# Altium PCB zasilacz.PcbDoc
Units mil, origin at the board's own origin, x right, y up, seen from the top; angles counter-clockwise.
Board outline 8820.03 x 6925.02 mil, 2 copper layers (Top Layer, Bottom Layer); 56 components, 28 nets, 174 pads, 4 vias.
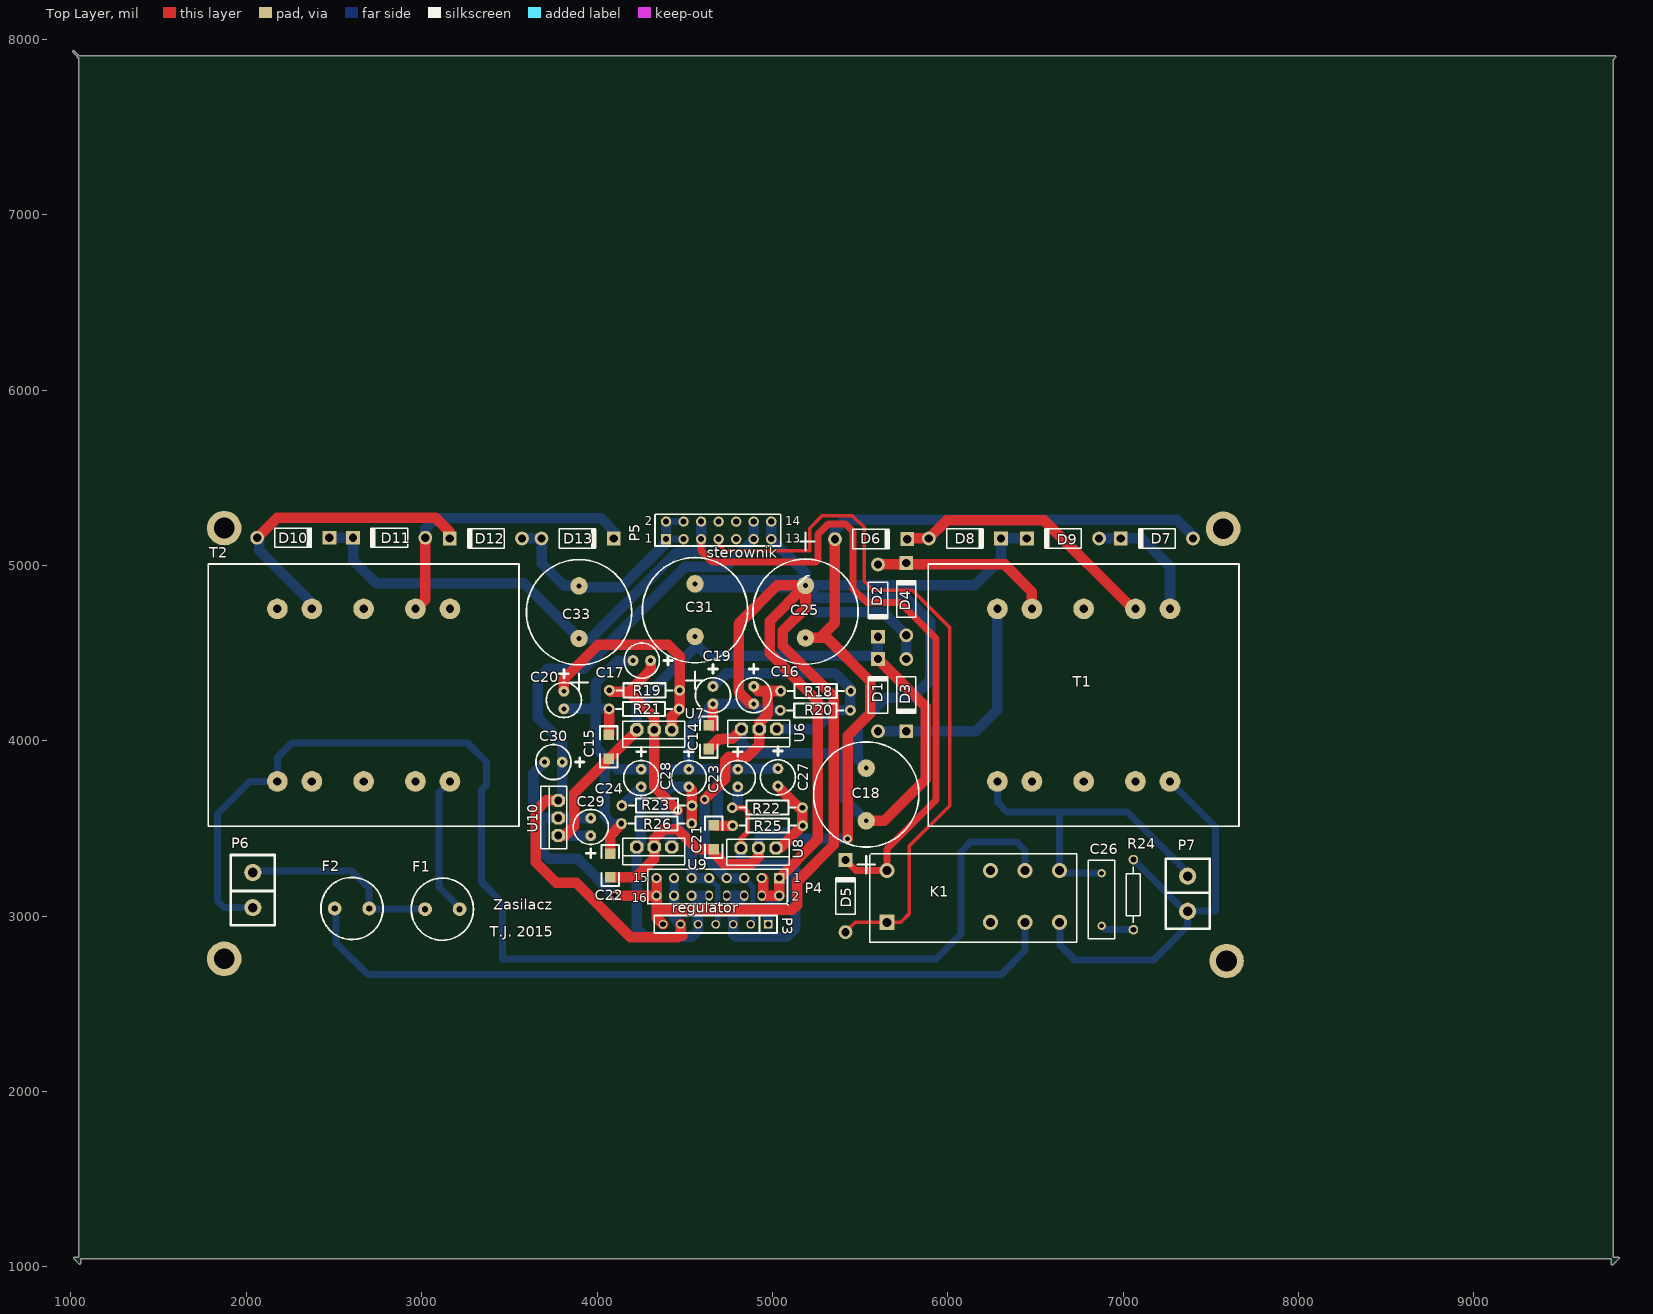
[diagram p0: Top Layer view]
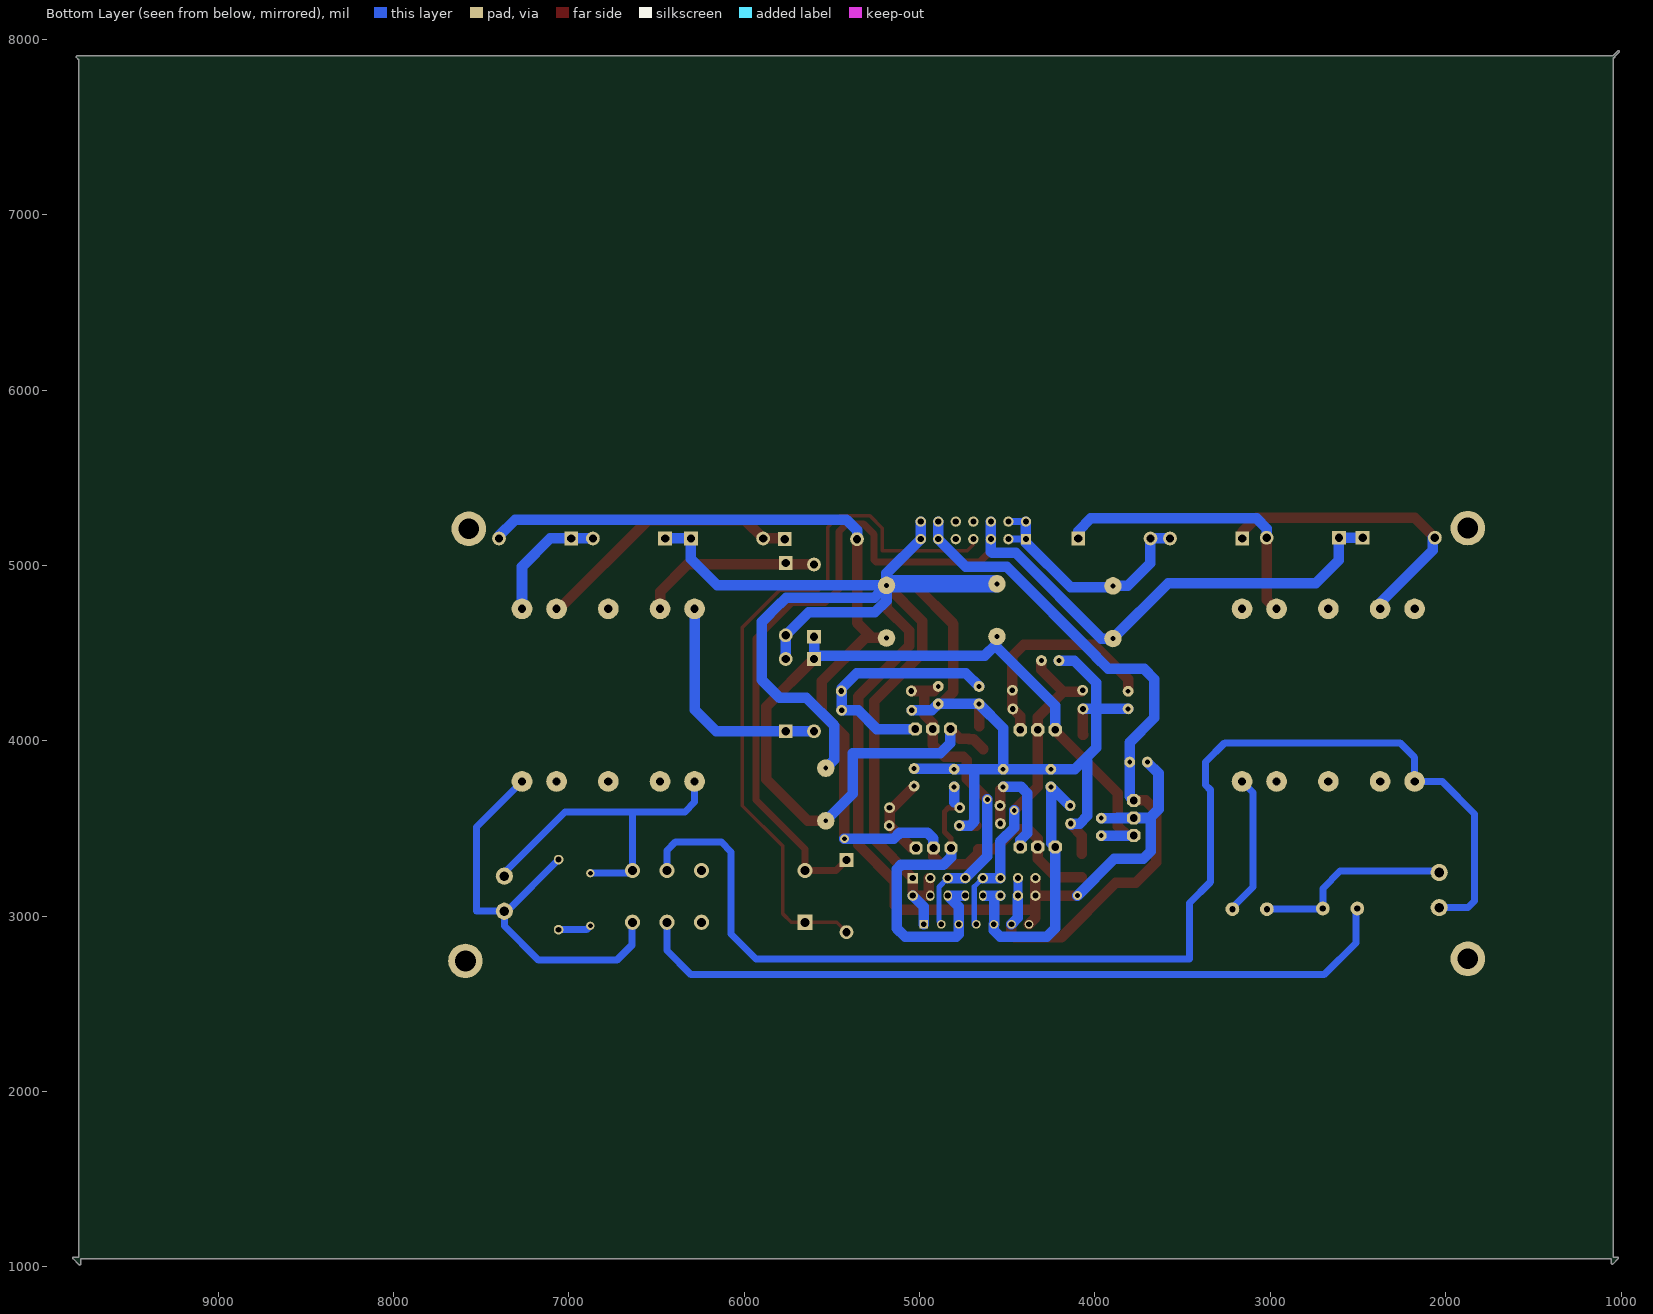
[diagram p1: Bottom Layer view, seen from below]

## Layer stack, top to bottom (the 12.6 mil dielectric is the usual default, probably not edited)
Top Solder: solder mask 0.4, Solder Resist, Dk 3.5
Top Layer: signal copper 1.4
Dielectric 1: dielectric 12.6, FR-4, Dk 4.8
Bottom Layer: signal copper 1.4
Bottom Solder: solder mask 0.4, Solder Resist, Dk 3.5

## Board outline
1016.47,1046.44 cw(c1020,1050) 1020,1055.02 1044.98,1055.02 1044.98,7892.92 1042.92,7894.98 1040,7894.98 cw(c1040,7900) 1035.57,7902.34 1011.45,7926.45 cw(c1015,7930) 1018.55,7933.55 1047.08,7905.02 9805,7905.02 cw(c9805,7900) 9810.01,7900 cw(c9805,7900) 9808.53,7896.44 9808.55,7896.45 9795.01,7882.92 9795.01,1055.02 9825,1055.02 cw(c9825,1050) 9830.01,1050 cw(c9825,1050) 9828.53,1046.44 9828.55,1046.45 9793.55,1011.45 9793.56,1011.47 cw(c9790,1015) 9784.99,1015 9784.99,1044.98 1055.02,1044.98 1055.02,1020 cw(c1050,1020) 1046.44,1016.47 1046.45,1016.45

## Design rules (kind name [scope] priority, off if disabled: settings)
Clearance [All] p1: gap=10
PolygonConnect [All] p1: connectstyle=Relief reliefconductorwidth=10 reliefentries=4 polygonreliefangle="90 Angle" airgapwidth=10
RoomDefinition zasilacz [InComponentClass('zasilacz')] p1: confinementstyle=ConfineIn formatcopy=TRUE lockcomponents=FALSE outline 9875,1660 28675,1660 28675,4910 9875,4910
RoutingVias [All] p1: holewidth=28 width=50 viastyle="Through Hole" minholewidth=28 minwidth=50 maxholewidth=28 maxwidth=50
SolderMaskExpansion [All] p1: expansion=4
Width [All] p1: maxlimit=40 minlimit=40 preferedwidth=40
30 further rules are at their usual default settings.

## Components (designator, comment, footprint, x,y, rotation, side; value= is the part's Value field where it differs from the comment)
C14 "Cap" 1206 4637.8,3952.76 r90 top
C15 "Cap" 1206 4066.93,3897.64 r90 top
C16 "ELECTRO2" RB.1/.2 4893.7,4409.45 r90 top
C17 "ELECTRO2" RB.1/.2 4405.51,4456.69 r0 top
C18 "ELECTRO2" RB.3/.6 5535.43,3543.31 r270 top
C19 "ELECTRO2" RB.1/.2 4661.42,4409.45 r90 top
C20 "ELECTRO2" RB.1/.2 3811.02,4381.89 r90 top
C21 "Cap" 1206 4665.35,3381.89 r90 top
C22 "Cap" 1206 4074.8,3220.47 r90 top
C23 "ELECTRO2" RB.1/.2 4803.15,3937.01 r90 top
C24 "ELECTRO2" RB.1/.2 4251.97,3937.01 r90 top
C25 "ELECTRO2" RB.3/.6 5188.98,4885.83 r90 top
C26 "Cap" RAD-0.3 6877.95,3094.49 r90 top
C27 "ELECTRO2" RB.1/.2 5031.5,3940.94 r90 top
C28 "ELECTRO2" RB.1/.2 4523.62,3937.01 r90 top
C29 "ELECTRO2" RB.1/.2 3964.57,3358.27 r270 top
C30 "ELECTRO2" RB.1/.2 3901.57,3877.95 r0 top
C31 "ELECTRO2" RB.3/.6 4559.06,4594.49 r270 top
C33 "ELECTRO2" RB.3/.6 3897.64,4582.68 r270 top
D1 "Diode 1N4001" DO-41 5602.36,4259.84 r90 top
D2 "Diode 1N4001" DO-41 5602.36,4799.21 r270 top
D3 "Diode 1N4001" DO-41 5763.78,4259.84 r270 top
D4 "Diode 1N4001" DO-41 5763.78,4807.09 r90 top
D5 "Diode 1N4007" DO-41 5417.32,3114.17 r90 top
D6 "Diode 1N4001" DO-41 5562.99,5149.61 r0 top
D7 "Diode 1N4001" DO-41 7192.91,5153.54 r180 top
D8 "Diode 1N4001" DO-41 6098.43,5153.54 r0 top
D9 "Diode 1N4001" DO-41 6657.48,5153.54 r180 top
D10 "Diode 1N4001" DO-41 2267.72,5157.48 r0 top
D11 "Diode 1N4001" DO-41 2814.96,5157.48 r180 top
D12 "Diode 1N4001" DO-41 3366.14,5153.54 r180 top
D13 "Diode 1N4001" DO-41 3889.76,5153.54 r0 top
F1 "Fuse 1" BEZP_OKR 3118.11,3039.37 r0 top
F2 "Fuse 1" BEZP_OKR 2602.36,3043.31 r180 top
K1 "Relay-DPDT" Prz_big 5653.54,2964.57 r90 top
P3 "regulator" SIP7 4976.38,2952.76 r180 top
P4 "regulator" HDR2X8 5039.37,3216.54 r180 top
P5 "sterownik" HDR2X7 4393.7,5149.61 r0 top
P6 "230VAC" ZLSRUB2-1 2066.93,3118.11 r90 top
P7 "230VAC_OUT" ZLSRUB2-1 7338.58,3157.48 r270 top
R18 "RES2" AXIAL0.4 5047.24,4283.46 r0 top
R19 "RES2" AXIAL0.4 4070.87,4287.4 r0 top
R20 "RES2" AXIAL0.4 5444.88,4173.23 r180 top
R21 "RES2" AXIAL0.4 4468.5,4181.1 r180 top
R22 "RES2" AXIAL0.4 4771.65,3618.11 r0 top
R23 "RES2" AXIAL0.4 4141.73,3629.92 r0 top
R24 "Res2" AXIAL-0.4 7059.06,3122.05 r270 top
R25 "RES2" AXIAL0.4 5173.23,3515.75 r180 top
R26 "RES2" AXIAL0.4 4539.37,3527.56 r180 top
T1 "trafo ZZ2" "TRAFO ZZ7" 6775.59,4259.84 r180 top
T2 "trafo ZZ1" "TRAFO ZZ7" 2669.29,4259.84 r180 top
U6 "LM317" 78XXST 5000,4051.18 r180 top
U7 "LM317" 78XXST 4401.57,4047.24 r180 top
U8 "LM337" 78XXST 4996.06,3374.02 r180 top
U9 "LM337" 78XXST 4401.57,3377.95 r180 top
U10 "7805" 78XXST 3763.78,3484.25 r90 top

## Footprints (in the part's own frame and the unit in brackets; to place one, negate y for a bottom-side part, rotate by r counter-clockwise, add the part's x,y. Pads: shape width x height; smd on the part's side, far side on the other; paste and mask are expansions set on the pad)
78XXST [mil]
  oct 75x75 hole 45: 1(-25,-15) 2(75,-15) 3(175,-15)
  silkscreen extent -100,-65 255,85
1206 [mil]
  rect 60x60 smd: 1(0,0) 2(135,0)
  silkscreen extent -50,-50 185,50
AXIAL0.4 [mil]
  round 62 hole 32: 1(0,0) 2(400,0)
  silkscreen extent 40,-40 360,40
AXIAL-0.4 [mm] "Axial Device, Thru-Hole; 2 Leads; 0.4 in Pin Spacing"
  round 1.4 hole 0.85: 1(-5.08,0) 2(5.08,0)
  silkscreen extent -4.06,-1.02 4.06,1.02
BEZP_OKR [mm]
  round 2 hole 0.9: 1(-2.5,0) 2(2.5,0)
  silkscreen extent -4.5,-4.5 4.5,4.5
DO-41 [mm] "Diode, Axial; Body 5.2 x 2.7 mm (LxDia. max), Lead Dia. 0.86 mm (max)"
  round 2 hole 1.2: 1(-5.23,0)
  rect 2x2 hole 1.2: 2(5.23,0)
  silkscreen extent -2.65,-1.4 2.75,1.4
HDR2X7 [mm] "Connector; Header; 7x2 Position"
  rect 1.5x1.5 hole 0.9: 1(0,0)
  round 1.5 hole 0.9: 2(0,2.54) 3(2.54,0) 4(2.54,2.54) 5(5.08,0) 6(5.08,2.54) 7(7.62,0) 8(7.62,2.54) 9(10.16,0) 10(10.16,2.54) 11(12.7,0) 12(12.7,2.54) 13(15.24,0) 14(15.24,2.54)
HDR2X8 [mm] "Connector; Header; 8x2 Position"
  rect 1.5x1.5 hole 0.9: 1(0,0)
  round 1.5 hole 0.9: 2(0,2.54) 3(2.54,0) 5(5.08,0) 7(7.62,0) 9(10.16,0) 11(12.7,0) 12(12.7,2.54) 13(15.24,0) 14(15.24,2.54) 15(17.78,0) 16(17.78,2.54)
  oval 1.2x1.5 hole 0.9: 4(2.54,2.54) 6(5.08,2.54)
  oval 1.1x1.5 hole 0.9: 8(7.62,2.54) 10(10.16,2.54)
  silkscreen extent 19.05,-1.27 19.05,3.81
Prz_big [mm]
  round 2.2 hole 1.3: 1(0,-20) 2(0,-15) 3(0,-25) 4(7.5,-20) 5(7.5,-15) 6(7.5,-25) 8(7.5,0)
  rect 2.2x2.2 hole 1.3: 7(0,0)
  silkscreen extent -2.92,-27.5 9.91,2.5
RAD-0.3 [mm] "Radial Cap, Thru-Hole; 2 Leads; 0.3 in Pin Spacing"
  round 1.2 hole 0.7: 1(-3.81,0) 2(3.81,0)
  silkscreen extent -5.71,-1.91 5.71,1.91
RB.1/.2 [mil]
  round 62 hole 28: 1(-100,0) 2(-200,0)
  silkscreen extent -250,-100 25,100
RB.3/.6 [mil]
  round 100 hole 28: 1(0,0) 2(-300,0)
  silkscreen extent -450,-300 300,300
SIP7 [mil]
  rect 50x50 hole 32: 1(0,0)
  round 50 hole 32: 2(100,0) 3(200,0) 4(300,0) 5(400,0) 6(500,0) 7(600,0)
  silkscreen extent -50,-50 650,50
"TRAFO ZZ7" [mm]
  round 3 hole 1.2: 1(-12.5,12.5) 2(-7.5,12.5) 3(0,12.5) 4(7.5,12.5) 5(12.5,12.5) 6(12.5,-12.5) 7(7.5,-12.5) 8(0,-12.5) 9(-7.5,-12.5) 10(-12.5,-12.5)
  silkscreen extent -22.5,-19 22.5,19
ZLSRUB2-1 [mil]
  round 98 hole 55: 1(-70,30) 2(130,30)
  silkscreen extent -170,-95 230,155

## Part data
C14 C15 C21 C22 C26: "Capacitor"
C16 C17 C18 C19 C20 C23 C24 C25 C27 C28 C29 C30 C31 C33: "Electrolytic Capacitor"
D1 D2 D3 D4 D5 D6 D7 D8 D9 D10 D11 D12 D13: "1 Amp General Purpose Rectifier"
F1 F2: "Fuse"
K1: "Dual-Pole Dual-Throw Relay"
P3: library part MHDR1X7, "Header, 7-Pin"
P4: library part "Header 8X2", "Header, 8-Pin, Dual row"
P5: library part "Header 7X2", "Header, 7-Pin, Dual row"
P6 P7: library part "Header 2", "Header, 2-Pin"
R24: "Resistor"
U10: library part 78XX

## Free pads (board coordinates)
  round 196.85 hole 118.11: 0(1874.02,2755.91) 0(1874.02,5212.6) 0(7570.87,5208.66) 0(7590.55,2744.09)

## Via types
v1: diameter 50, hole 28, Top Layer to Bottom Layer, 4 vias

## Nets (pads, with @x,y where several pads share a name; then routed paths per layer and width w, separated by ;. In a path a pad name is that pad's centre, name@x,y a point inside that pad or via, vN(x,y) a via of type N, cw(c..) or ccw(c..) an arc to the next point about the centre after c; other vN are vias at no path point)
230VAC1: K1.3 P7.2 R24.1 T1.1 | length 2498.3
  Bottom Layer w40: K1.3 6641.73,2960.63 6641.73,2833.54 6727.24,2748.03 7173.23,2748.03 7368.58,2943.39 P7.2 ; R24.1 7353.62,3027.48 P7.2 ; T1.1 7527.56,3507.87 7527.56,3027.56 7527.48,3027.48 P7.2
230VAC2: C26.2 K1.6 P7.1 T1.5 | length 1973.8
  Bottom Layer w40: T1.5 6283.46,3649.61 6338.58,3594.49 6641.73,3594.49 ; C26.2 6653.15,3244.49 K1.6 6637.8,3590.55 6641.73,3594.49 ; P7.1 7368.58,3249.53 7023.62,3594.49 6641.73,3594.49
230VAC3: F1.2 T2.1 | length 801.1
  Bottom Layer w40: T2.1 3098.43,3704.72 3098.43,3165.35 F1.2@3220.47,3043.31
230VAC4: F2.2 K1.1 | length 4431.3
  Bottom Layer w40: F2.2@2511.81,3055.12 2511.81,2846.46 2692.91,2665.35 6303.15,2665.35 6440.94,2803.15 K1.1
230VAC5: K1.4 P6.1 T2.5 | length 7390.6
  Bottom Layer w40: P6.1 1873.15,3048.11 1834.65,3086.61 1834.65,3582.68 2019.68,3767.72 T2.5 2177.17,3905.51 2259.84,3988.19 3259.84,3988.19 3370.08,3877.95 3370.08,3748.03 3342.52,3720.47 3342.52,3192.91 3460.63,3074.8 3460.63,2755.91 5933.07,2755.91 6074.8,2897.64 6074.8,3366.14 6129.92,3421.26 6393.7,3421.26 6440.94,3374.02 K1.4
+5VA: C17.1 P3.4 P4.9 P4.11 R19.1 U7.2 | length 1941.9
  Top Layer w60: R19.1 4078.74,4279.53 4181.1,4279.53 ; C17.1 4305.51,4403.94 4181.1,4279.53 ; v1(4460.63,3602.36) 4326.57,3736.42 U7.2 4326.57,4134.06 4181.1,4279.53
  Bottom Layer w30: P4.9 4688.98,3166.93 P3.4@4688.98,2948.82
  Bottom Layer w60: v1(4460.63,3602.36) 4460.63,3503.94 4539.37,3425.2 P4.11 P4.9
+5VDA: C30.1 P3.6 P4.13 P4.14 P5.11 P5.12 U10.3 | length 4244.9
  Top Layer w60: U10.3 3710.43,3659.25 3649.61,3598.43 3649.61,3307.09 3767.72,3188.98 3881.89,3188.98 4192.91,2877.95 4456.69,2877.95 4476.38,2897.64 ; P3.6 4476.38,2897.64 ; 4486.26,2887.76 4476.38,2897.64
  Bottom Layer w50: P4.14 P4.13
  Bottom Layer w60: U10.3 3801.57,3682.05 C30.1 3801.57,3989.76 3661.42,4129.92 3661.42,4350.39 3720.47,4409.45 3925.2,4409.45 3998.9,4483.15 ; 3986.22,4474.41 4503.94,4992.13 4736.22,4992.13 P5.11 P5.12 ; P4.14 4439.37,2989.76 P3.6
+12VA: C16.1 P3.2 P4.5 P4.7 R18.1 U6.2 | length 1935.2
  Top Layer w60: v1(4614.17,3665.35) 4732.15,3783.33 4732.15,3889.63 4750.53,3908.01 4856.83,3908.01 4925,3976.18 U6.2 4925,4100.72 4973.88,4149.61 4973.88,4280.97 5044.75,4280.97 R18.1 4919.69,4283.46 C16.1
  Bottom Layer w30: P4.5 4889.76,3166.14 P3.2@4889.76,2968.5
  Bottom Layer w60: v1(4614.17,3665.35) 4614.17,3341.73 P4.7 P4.5
+VDD: C33.1 D5.2 D10.2 D11.2 K1.8 P5.5 P5.6 | length 6580
  Top Layer w40: P5.5 4593.7,5083.46 4657.48,5019.69 5248.03,5019.69 5259.84,5031.5 5259.84,5177.17 5318.9,5236.22 5417.32,5236.22 5460.63,5192.91 5460.63,4866.14 5539.37,4787.4 5728.35,4787.4 5933.07,4582.68 5933.07,4224.77 5934.02,4223.83 5934.02,3662.36 5653.54,3381.89 K1.8 5477.56,3259.84 D5.2
  Bottom Layer w40: 4586.61,5070.87 4593.7,5077.95
  Bottom Layer w60: D10.2 D11.2 2609.06,5028.74 2740.16,4897.64 3582.68,4897.64 C33.1 3964.57,4582.68 4452.76,5070.87 4586.61,5070.87 ; 4593.7,5077.95 P5.5 P5.6
-5VA: C24.2 P3.5 P4.10 P4.12 R23.1 U9.3 | length 1627.3
  Bottom Layer w60: R23.1@4144.88,3629.92 C24.2@4249.07,3734.11 ; C24.2 C24.2@4249.07,3734.11 ; P4.12 P4.10@4625.98,3116.54 ; 4574.8,3110.24 4574.8,2954.33 P3.5 4576.38,2918.9 4540.24,2882.76 4274.72,2882.76 4226.57,2930.91 U9.3 4249.07,3415.45 C24.2@4249.07,3734.11
-12VA: C23.2 P3.3 P4.6 P4.8 R22.1 U8.3 | length 1831.8
  Top Layer w30: R22.1 4834.65,3618.11 4858.27,3594.49 4858.27,3480.31 4821.06,3443.11 U8.3
  Bottom Layer w60: P4.8@4748.03,3116.54 4826.77,3116.54 4826.77,3103.94 4776.38,3053.54 P3.3 4776.38,2896.85 4791.34,2881.89 5082.68,2881.89 5129.92,2929.13 5129.92,3267.72 5106.3,3291.34 4866.14,3291.34 4821.06,3336.42 U8.3 ; 4803.15,3649.61 C23.2
ADGND: C14.2 C15.2 C16.2 C17.2 C18.2 C19.2 C20.2 C21.2 C22.2 C23.1 C24.1 C25.1 C27.1 C28.1 C29.2 C30.2 C31.2 D3.1 D4.1 D8.2 D9.2 P3.1 P3.7 P4.1 P4.2 P4.3 P4.4 P4.15 P4.16 P5.13 P5.14 R20.2 R21.2 R25.2 R26.2 U10.2 | length 17653.8
  Top Layer w60: C15.2 4068.5,4034.21 R21.2 ; C22.2 4074.8,3459.05 R26.2@4135.43,3519.68 ; v1(4100,3116.54) P4.16 ; P4.15 P4.16 ; P3.7 4339.37,2989.76 4339.37,3035.43 ; C14.2@4661.42,4083.82 C19.2 ; C21.2@4676.02,3515.75 R25.2 ; C16.2 4877.17,4209.45 4807.09,4279.53 4807.09,4665.35 5027.56,4885.83 C25.1 ; P4.3@4947.24,3216.54 4947.24,3116.54 P4.2 P4.1 5259.84,3437.01 5259.84,4224.41 4984.25,4500 4984.25,4681.1 C25.1 ; 4339.37,3035.43 P4.16 ; 4339.37,3035.43 5114.17,3035.43 5141.73,3062.99 5141.73,3196.85 5350.39,3405.51 5350.39,4251.97 5060.1,4542.27 5060.1,4627.03 5188.98,4755.91 C25.1
  Bottom Layer w60: 3681.1,3566.93 3681.1,3370.08 3724.41,3326.77 3889.76,3326.77 v1(4100,3116.54) ; C30.2 3637.8,3814.17 3637.8,3610.24 3688.78,3559.25 U10.2 3870.28,3559.25 3871.26,3558.27 C29.2 ; C20.2 3992.13,4181.89 ; 4043.31,3881.89 4043.31,3570.87 4086.61,3527.56 4127.56,3527.56 R26.2@4135.43,3519.68 ; R21.2@4067.72,4181.89 3992.13,4181.89 ; C17.2 4118.11,4456.69 3992.13,4330.71 3992.13,4181.89 ; C24.1 4115.75,3837.01 3992.13,3960.63 3992.13,4181.89 ; C24.1@4259.84,3837.01 C28.1 ; 4669.29,3837.01 C28.1 ; R25.2 4712.6,3515.75 4688.98,3539.37 4688.98,3837.01 C23.1 4807.09,3840.94 C27.1 ; P3.1 4976.38,3053.54 P4.2 ; P5.14 P5.13 5188.98,4954.33 C25.1 ; R20.2 4929.92,4173.23 C16.2 C19.2 4523.62,4071.65 C28.1 ; C25.1@5180.31,4894.49 C25.1 ; C18.2 5488.19,3890.55 5488.19,4086.61 5645.67,4244.09 5799.21,4244.09 5901.57,4346.46 5901.57,4677.17 5795.28,4783.46 5791.34,4783.46 5759.84,4814.96 5259.84,4814.96 C25.1 ; D3.1@5763.78,4477.56 D4.1 5632.68,4732.28 5255.91,4732.28 5188.98,4799.21 C25.1 ; D9.2 D8.2 6304.33,5036.61 6153.54,4885.83 C25.1
  Bottom Layer w100: C31.2@4562.99,4894.49 C25.1@5180.31,4894.49
DGND: C33.2 D12.1 D13.1 P5.1 P5.2 P5.3 P5.4 | length 1445.5
  Bottom Layer w40: P5.1 P5.3 ; P5.2 P5.4
  Bottom Layer w60: D12.1 D13.1 3683.86,5012.99 3814.17,4882.68 C33.2 3906.3,4874.02 4137.8,4874.02 4393.7,5129.92 P5.1 P5.2
NetC14_1: C14.1 C15.1 C18.1 C29.1 C31.1 D1.2 D2.2 U6.3 U7.3 U10.1 | length 5450.7
  Top Layer w60: U10.1@3779.76,3458.27 U10.1 3817.52,3459.25 3870.08,3511.81 3870.08,3700.79 C15.1 4226.57,4057.28 U7.3 ; C14.1 4692.91,4007.87 4716.54,4007.87 4720.47,4011.81 4770.63,4011.81 U6.3 ; C18.1 5637.8,3543.31 5874.02,3779.53 5874.02,4194.09 D1.2
  Bottom Layer w60: U10.1@3779.76,3458.27 C29.1 ; U7.3 4226.57,4199.02 4562.99,4535.43 C31.1@4562.99,4551.18 ; C31.1@4562.99,4594.49 C31.1@4562.99,4551.18 ; U6.3 4825,3986.02 4881.89,3929.13 5381.89,3929.13 5381.89,3696.85 C18.1 ; D2.2 D1.2 5583.86,4484.25 4629.92,4484.25 C31.1@4562.99,4551.18
NetC19_1: C19.1 R18.2 R20.1 U6.1 | length 1441.2
  Bottom Layer w60: C19.1 4737.8,4385.83 5358.27,4385.83 5444.88,4299.21 R20.1 5350.39,4173.23 5243.35,4066.18 U6.1
NetC20_1: C20.1 R19.2 R21.1 U7.1 | length 1274.9
  Top Layer w60: C20.1 3811.02,4350.39 4007.87,4547.24 4405.51,4547.24 4470.87,4481.89 R19.2 4470.87,4183.46 R21.1 4426.57,4139.17 U7.1
NetC21_1: C21.1 C22.1 C25.2 D6.1 D7.1 U8.2 U9.2 | length 5974.7
  Top Layer w60: C22.1 4220.47,3220.47 4326.57,3326.57 U9.2 4326.57,3440.75 4381.89,3496.06 4456.69,3496.06 4570.87,3381.89 C21.1 4665.35,3358.27 4728.35,3295.28 4877.95,3295.28 4921.06,3338.39 U8.2 ; C25.2 5270.87,4585.83 ; D6.1 5357.09,4672.05 5270.87,4585.83 ; v1(5429.13,3440.94) 5429.13,4027.56 5559.06,4157.48 5559.06,4338.58 5311.81,4585.83 5270.87,4585.83
  Bottom Layer w60: U8.2 4921.06,3440.75 4956.69,3476.38 5112.19,3476.38 5147.62,3440.94 v1(5429.13,3440.94) ; D6.1 5357.09,5199.61 5417.32,5259.84 7307.09,5259.84 7398.82,5168.11 D7.1
NetC26_1: C26.1 R24.2 | length 190.4
  Bottom Layer w40: C26.1 6900.39,2922.05 R24.2
NetC27_2: C27.2 R22.2 R25.1 U8.1 | length 487.3
  Top Layer w60: U8.1 5046.5,3389.02 5171.65,3514.17 5171.65,3600.79 C27.2
NetC28_2: C28.2 R23.2 R26.1 U9.1 | length 693.5
  Top Layer w60: C28.2 4539.37,3721.26 R26.1
  Bottom Layer w60: U9.1 4426.57,3431.69 4385.83,3472.44 4385.83,3700.79 4422.05,3737.01 C28.2
NetD1_1: D1.1 D3.2 T1.6 | length 1306.9
  Bottom Layer w60: D1.1 D3.2 6160.24,4053.94 6283.46,4177.17 T1.6
NetD2_1: D2.1 D4.2 T1.7 | length 1040.5
  Top Layer w60: D2.1 6325.59,5005.12 6480.31,4850.39 T1.7
NetD6_2: D6.2 D8.1 T1.9 | length 1554.7
  Top Layer w60: D6.2 5772.83,5153.54 D8.1 5994.88,5255.91 6551.18,5255.91 7055.12,4751.97 T1.9
NetD7_2: D7.2 D9.1 T1.10 | length 711.3
  Bottom Layer w60: D9.1 D7.2 7106.3,5153.54 7267.72,4992.13 T1.10
NetD10_1: D10.1 D12.2 T2.7 | length 1745.5
  Top Layer w40: D12.2 D12.2@3160.24,5190.16
  Top Layer w60: D10.1 2175.98,5271.65 3078.74,5271.65 D12.2@3160.24,5190.16
  Bottom Layer w40: T2.7 T2.7@2374.02,4787.4
  Bottom Layer w60: D10.1@2074.8,5157.48 2074.8,5086.61 T2.7@2374.02,4787.4
NetD11_1: D11.1 D13.2 T2.9 | length 1654.9
  Top Layer w60: T2.9@2968.5,4751.97 3019.68,4803.15 D11.1@3019.68,5154.72
  Bottom Layer w40: T2.9 T2.9@2968.5,4751.97 ; D11.1 D11.1@3023.62,5154.72 ; D13.2 4095.67,5195.67
  Bottom Layer w60: D11.1 3020.87,5209.84 3078.74,5267.72 4023.62,5267.72 4095.67,5195.67
NetF1_1: F1.1 F2.1 P6.2 | length 1141.6
  Bottom Layer w40: P6.2@2036.93,3255.91 2602.36,3255.91 2700.79,3157.48 F2.1 ; F2.1@2696.85,3039.37 F1.1
STDBYO: D5.1 K1.7 P5.7 | length 4103.3
  Top Layer w10: 4693.7,5117.32 P5.7
  Top Layer w20: 4693.7,5117.32 4728.35,5082.68 5212.6,5082.68 5212.6,5212.6 5283.46,5283.46 5456.69,5283.46 5523.62,5216.54 5523.62,4909.45 5574.8,4858.27 5799.21,4858.27 6011.81,4645.67 6011.81,3629.92 5779.53,3397.64 5779.53,3011.81 5732.28,2964.57 K1.7 5473.62,2964.57 D5.1
pads on no net: K1.2 K1.5 P5.8 P5.9 P5.10 T1.2 T1.3 T1.4 T1.8 T2.2 T2.3 T2.4 T2.6 T2.8 T2.10

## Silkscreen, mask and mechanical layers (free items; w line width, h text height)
Top Overlay:
  lines w10: 4289.37,3070.87 5082.68,3070.87 5090.55,3062.99 ; 4289.37,3266.54 5085.43,3266.54 5086.61,3267.72 5086.61,3082.68 5082.68,3078.74 ; 5145.67,4889.76 5188.98,4933.07 ; 5177.17,4921.26 5196.85,4940.94 5208.66,4940.94 ; 4330.71,5110.24 5047.24,5110.24 5047.24,5287.4 5043.31,5291.34 4346.46,5291.34 4334.65,5291.34 4330.71,5287.4 4330.71,5110.24
  text "Zasilacz" at 3409.45,3035.43 h60
  text "T.J. 2015" at 3389.76,2881.89 h60
Bottom Solder:
  lines w10: 1771.65,2653.54 7677.17,2653.54 7677.17,5314.96 1771.65,5314.96 1771.65,2653.54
